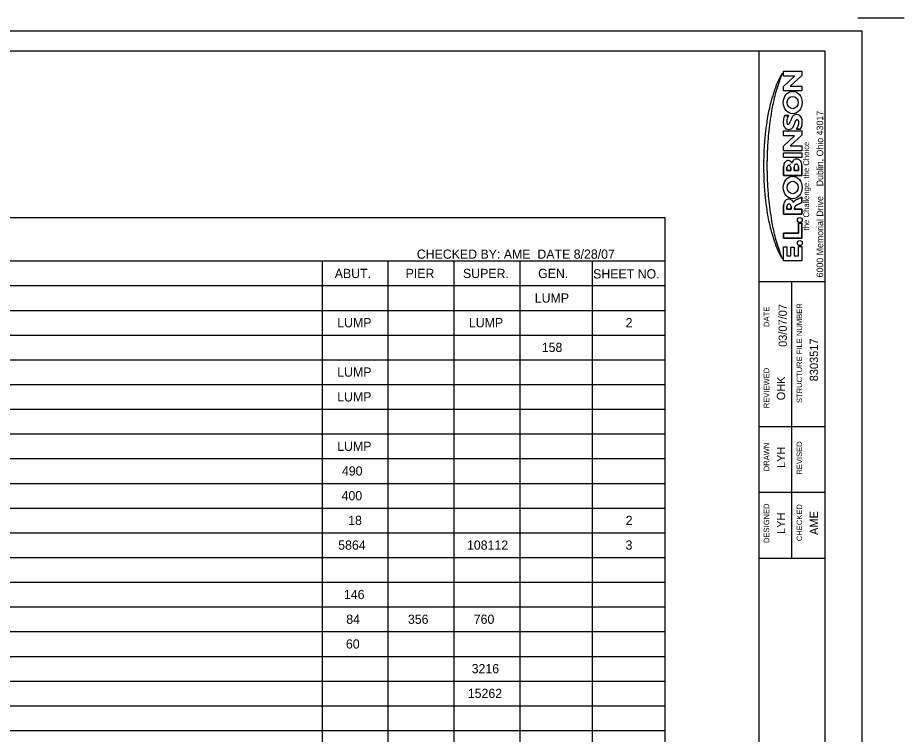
# Model space of a CAD drawing. Extents: x -70.8 to -34.9, y -11.1 to 10.9.
# Drawn here: x -48.33 to -34.87, y -0.02 to 10.86 of the extents above; entities that cross this region are included whole.
import ezdxf

# ---------------------------------------------------------------- set-up
doc = ezdxf.new("R2010")
doc.units = 0
for name, color, linetype in [('BR_P_Gen_Ground_Slope', 7, 'Continuous'), ('BR_P_Gen_Text', 7, 'Continuous'), ('Default', 7, 'Continuous'), ('SH_Border', 7, 'Continuous'), ('SH_Cut_Line', 7, 'Continuous'), ('SH_Data', 7, 'Continuous')]:
    doc.layers.add(name, color=color, linetype=linetype)

msp = doc.modelspace()

# ---------------------------------------------------------------- linework, layer by layer
at = {"layer": 'BR_P_Gen_Ground_Slope'}
for p, q in [((-66.205, 7.824), (-38.5, 7.824)), ((-38.5, 7.824), (-38.5, -8.584)), ((-66.205, 7.166), (-38.5, 7.166)), ((-43.705, 7.166), (-43.705, -8.584)), ((-42.705, 7.166), (-42.705, -8.584)), ((-41.705, 7.166), (-41.705, -8.584)), ((-40.705, 7.166), (-40.705, -8.584)), ((-39.603, 7.166), (-39.603, -8.584)), ((-66.205, 6.791), (-38.5, 6.791)), ((-66.205, 6.416), (-38.5, 6.416)), ((-66.205, 6.041), (-38.5, 6.041)), ((-66.205, 5.666), (-38.5, 5.666)), ((-66.205, 5.291), (-38.5, 5.291)), ((-66.205, 4.916), (-38.5, 4.916)), ((-66.205, 4.541), (-38.5, 4.541)), ((-66.205, 4.166), (-38.5, 4.166)), ((-66.205, 3.791), (-38.5, 3.791)), ((-66.205, 3.416), (-38.5, 3.416)), ((-66.205, 3.041), (-38.5, 3.041)), ((-66.205, 2.666), (-38.5, 2.666)), ((-66.205, 2.291), (-38.5, 2.291)), ((-66.205, 1.916), (-38.5, 1.916)), ((-66.205, 1.541), (-38.5, 1.541)), ((-66.205, 1.166), (-38.5, 1.166)), ((-66.205, 0.791), (-38.5, 0.791)), ((-66.205, 0.416), (-38.5, 0.416)), ((-66.205, 0.041), (-38.5, 0.041))]:
    msp.add_line(p, q, dxfattribs=at)
at = {"layer": 'Default'}
for p, q in [((-36.442, 9.166), (-36.504, 9.166)), ((-36.504, 9.166), (-36.442, 9.166)), ((-36.698, 8.462), (-36.698, 8.597)), ((-36.647, 8.583), (-36.647, 8.537)), ((-36.647, 8.537), (-36.647, 8.583)), ((-36.42, 8.612), (-36.42, 8.462)), ((-36.42, 8.462), (-36.698, 8.462)), ((-36.648, 7.992), (-36.648, 7.949)), ((-36.648, 7.949), (-36.648, 7.992)), ((-36.648, 7.949), (-36.585, 7.949)), ((-36.585, 7.949), (-36.648, 7.949)), ((-36.585, 7.949), (-36.585, 7.992)), ((-36.585, 7.992), (-36.585, 7.949)), ((-36.42, 8.052), (-36.501, 8.013)), ((-36.501, 8.013), (-36.42, 8.052))]:
    msp.add_line(p, q, dxfattribs=at)
for points in [[(-36.42, 9.746), (-36.698, 9.746), (-36.698, 9.815), (-36.53, 9.971), (-36.698, 9.971), (-36.698, 10.046), (-36.42, 10.046), (-36.42, 9.981), (-36.597, 9.82), (-36.42, 9.82)], [(-36.42, 8.838), (-36.698, 8.838), (-36.698, 8.907), (-36.53, 9.063), (-36.698, 9.063), (-36.698, 9.138), (-36.42, 9.138), (-36.42, 9.073), (-36.597, 8.912), (-36.42, 8.912)], [(-36.698, 8.734), (-36.698, 8.808), (-36.42, 8.808), (-36.42, 8.734)], [(-36.698, 7.167), (-36.698, 7.381), (-36.647, 7.381), (-36.647, 7.242), (-36.59, 7.242), (-36.59, 7.374), (-36.538, 7.374), (-36.538, 7.242), (-36.471, 7.242), (-36.471, 7.384), (-36.42, 7.384), (-36.42, 7.167)]]:
    msp.add_lwpolyline(points, close=True, dxfattribs=at)
for points in [[(-36.681, 9.373), (-36.625, 9.373), (-36.636, 9.346)], [(-36.636, 9.346), (-36.625, 9.373), (-36.681, 9.373)], [(-36.42, 8.612), (-36.42, 8.462), (-36.698, 8.462), (-36.698, 8.597)], [(-36.698, 8.597), (-36.698, 8.462), (-36.42, 8.462)], [(-36.647, 8.537), (-36.588, 8.537), (-36.588, 8.583)], [(-36.588, 8.583), (-36.588, 8.537), (-36.647, 8.537)], [(-36.537, 8.592), (-36.537, 8.537), (-36.472, 8.537), (-36.472, 8.592)], [(-36.472, 8.592), (-36.472, 8.537), (-36.537, 8.537), (-36.537, 8.592)], [(-36.42, 8.462), (-36.42, 8.612)], [(-36.485, 8.102), (-36.42, 8.134), (-36.42, 8.052)], [(-36.42, 8.052), (-36.42, 8.134), (-36.485, 8.102)], [(-36.533, 7.971), (-36.533, 7.949), (-36.42, 7.949), (-36.42, 7.874), (-36.698, 7.874), (-36.698, 7.949), (-36.698, 8.013)], [(-36.698, 8.013), (-36.698, 7.949), (-36.698, 7.874), (-36.42, 7.874)], [(-36.648, 7.992), (-36.648, 7.949), (-36.585, 7.949), (-36.585, 7.992)], [(-36.42, 7.874), (-36.42, 7.949), (-36.533, 7.949), (-36.533, 7.971)], [(-36.698, 7.51), (-36.698, 7.585), (-36.471, 7.585), (-36.471, 7.737), (-36.42, 7.737), (-36.42, 7.51), (-36.698, 7.51)], [(-36.42, 7.737), (-36.471, 7.737), (-36.471, 7.585), (-36.698, 7.585), (-36.698, 7.51)], [(-36.698, 7.51), (-36.42, 7.51), (-36.42, 7.737)]]:
    msp.add_lwpolyline(points, dxfattribs=at)
for centre, major_axis, ratio, start_param, end_param in [((-35.936, 9.339), (0, 1.141), 0.85, 0.988431, 1.105191), ((-35.936, 9.339), (0, 1.141), 0.85, 0.988431, 1.105191), ((-75.2, 31.113), (0, 49.953), 0.85, 4.274094, 4.276309), ((-75.2, 31.113), (0, 49.953), 0.85, 4.274094, 4.276309), ((-36.488, 9.767), (0, 0.363), 0.85, 0.822588, 0.988431), ((-36.488, 9.767), (0, 0.363), 0.85, 0.822588, 0.988431), ((-35.457, 9.198), (0, 1.685), 0.85, 1.132502, 1.288747), ((-35.457, 9.198), (0, 1.685), 0.85, 1.132502, 1.288747), ((-36.359, 9.589), (0, 0.583), 0.85, 1.105191, 1.165908), ((-36.359, 9.589), (0, 0.583), 0.85, 1.105191, 1.165908), ((-34.383, 8.593), (0, 3.112), 0.85, 1.165908, 1.233316), ((-34.383, 8.593), (0, 3.112), 0.85, 1.165908, 1.233316), ((-35.174, 8.941), (0, 2.119), 0.85, 1.243005, 1.347881), ((-35.174, 8.941), (0, 2.119), 0.85, 1.243005, 1.347881), ((-33.959, 8.688), (0, 3.52), 0.85, 1.288747, 1.354281), ((-33.959, 8.688), (0, 3.52), 0.85, 1.288747, 1.354281), ((-36.56, 9.569), (0, -0.0938), 0.910305, 4.71238898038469, 4.712389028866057), ((-32.74, 8.494), (0, 4.963), 0.85, 1.378198, 1.448475), ((-32.74, 8.494), (0, 4.963), 0.85, 1.378198, 1.448475), ((-33.985, 8.671), (0, 3.544), 0.85, 1.360764, 1.426378), ((-33.985, 8.671), (0, 3.544), 0.85, 1.360764, 1.426378), ((-36.541, 9.273), (0, 0.19), 0.85, 1.320154, 1.737094), ((-36.541, 9.273), (0, 0.19), 0.85, 1.320154, 1.737094), ((-36.528, 9.27), (0, 0.206), 0.85, 1.108668, 1.320154), ((-36.528, 9.27), (0, 0.206), 0.85, 1.108668, 1.320154), ((-36.819, 9.44), (0, 0.176), 0.85, 4.250261, 4.3216), ((-36.819, 9.44), (0, 0.176), 0.85, 4.250261, 4.3216), ((-36.556, 9.282), (0, 0.111), 0.85, 1.456901, 1.818883), ((-36.556, 9.282), (0, 0.111), 0.85, 1.456901, 1.818883), ((-36.553, 9.282), (0, 0.115), 0.85, 1.297264, 1.456901), ((-36.553, 9.282), (0, 0.115), 0.85, 1.297264, 1.456901), ((-36.487, 9.26), (0, 0.196), 0.85, 1.114999, 1.297264), ((-36.487, 9.26), (0, 0.196), 0.85, 1.114999, 1.297264), ((-36.727, 9.34), (0, 0.165), 0.85, 4.175459, 4.396402), ((-36.727, 9.34), (0, 0.165), 0.85, 4.175459, 4.396402), ((-36.401, 9.215), (0, 0.238), 0.85, 1.030221, 1.254809), ((-36.401, 9.215), (0, 0.238), 0.85, 1.030221, 1.254809), ((-36.495, 9.281), (0, 0.11), 0.85, 0.486829, 1.030221), ((-36.495, 9.281), (0, 0.11), 0.85, 0.486829, 1.030221), ((-36.56, 9.569), (0, -0.17), 0.841969, 0, 4.84813681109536e-08), ((-36.508, 9.31), (0, 0.0761), 0.85, 0.083326, 0.486829), ((-36.508, 9.31), (0, 0.0761), 0.85, 0.083326, 0.486829), ((-36.304, 9.156), (0, 0.284), 0.85, 1.063855, 1.164639), ((-36.304, 9.156), (0, 0.284), 0.85, 1.063855, 1.164639), ((-36.492, 9.279), (0, 0.0304), 0.85, 0.715581, 1.063855), ((-36.492, 9.279), (0, 0.0304), 0.85, 0.715581, 1.063855), ((-36.503, 9.233), (0, 0.154), 0.85, 6.083659, 6.366511), ((-36.503, 9.233), (0, 0.154), 0.85, 6.083659, 6.366511), ((-36.491, 9.278), (0, 0.0317), 0.85, 0.212074, 0.715581), ((-36.491, 9.278), (0, 0.0317), 0.85, 0.212074, 0.715581), ((-36.492, 9.283), (0, 0.026), 0.85, 5.247627, 6.495259), ((-36.492, 9.283), (0, 0.026), 0.85, 5.247627, 6.495259), ((-36.489, 9.311), (0, 0.0741), 0.85, 5.529173, 6.083659), ((-36.489, 9.311), (0, 0.0741), 0.85, 5.529173, 6.083659), ((-36.509, 9.272), (0, 0.0483), 0.85, 4.86616, 5.247627), ((-36.509, 9.272), (0, 0.0483), 0.85, 4.86616, 5.247627), ((-36.509, 9.286), (0, 0.109), 0.85, 4.887723, 5.529173), ((-36.509, 9.286), (0, 0.109), 0.85, 4.887723, 5.529174), ((-36.589, 9.269), (0, 0.205), 0.85, 4.51081, 4.887723), ((-36.589, 9.269), (0, 0.205), 0.85, 4.51081, 4.887723), ((-35.406, 8.848), (0, 1.866), 0.85, 1.391456, 1.496401), ((-35.406, 8.848), (0, 1.866), 0.85, 1.391456, 1.496401), ((-36.609, 9.26), (0, 0.11), 0.85, 1.737094, 2.325359), ((-36.609, 9.26), (0, 0.11), 0.85, 1.737094, 2.325359), ((-36.629, 9.237), (0, 0.0764), 0.85, 2.325359, 2.878408), ((-36.629, 9.237), (0, 0.0764), 0.85, 2.325359, 2.878408), ((-36.625, 9.262), (0, 0.0279), 0.85, 1.818883, 2.384672), ((-36.625, 9.262), (0, 0.0279), 0.85, 1.818883, 2.384672), ((-36.621, 9.273), (0, 0.113), 0.85, 2.878408, 3.55749), ((-36.621, 9.273), (0, 0.113), 0.85, 2.878408, 3.55749), ((-36.63, 9.256), (0, 0.0197), 0.85, 2.384672, 3.137191), ((-36.63, 9.256), (0, 0.0197), 0.85, 2.384672, 3.137191), ((-36.63, 9.264), (0, 0.0276), 0.85, 3.137191, 4.01614), ((-36.63, 9.264), (0, 0.0276), 0.85, 3.137191, 4.01614), ((-36.658, 9.292), (0, 0.071), 0.85, 4.01614, 4.175459), ((-36.658, 9.292), (0, 0.071), 0.85, 4.01614, 4.175459), ((-36.608, 9.237), (0, 0.0738), 0.85, 3.55749, 3.971659), ((-36.608, 9.237), (0, 0.0738), 0.85, 3.55749, 3.971659), ((-36.652, 9.285), (0, 0.145), 0.85, 3.971659, 4.353371), ((-36.652, 9.285), (0, 0.145), 0.85, 3.971659, 4.353371), ((-35.918, 8.96), (0, 0.778), 0.85, 1.164639, 1.211778), ((-35.918, 8.96), (0, 0.778), 0.85, 1.164639, 1.211778), ((-36.681, 9.328), (0, 0.265), 0.85, 4.050165, 4.172563), ((-36.681, 9.328), (0, 0.265), 0.85, 4.050165, 4.172563), ((-36.758, 9.382), (0, 0.37), 0.85, 4.172563, 4.251833), ((-36.758, 9.382), (0, 0.37), 0.85, 4.172563, 4.251833), ((-36.554, 9.264), (0, 0.103), 0.85, 4.251833, 4.86616), ((-36.554, 9.264), (0, 0.103), 0.85, 4.251833, 4.86616), ((-36.547, 9.255), (0, 0.152), 0.85, 4.087438, 4.318356), ((-36.547, 9.255), (0, 0.152), 0.85, 4.087438, 4.318356), ((-36.563, 9.263), (0, 0.173), 0.85, 4.318356, 4.51081), ((-36.563, 9.263), (0, 0.173), 0.85, 4.318356, 4.51081), ((-31.142, 8.427), (0, 6.84), 0.85, 1.472392, 1.505619), ((-31.142, 8.427), (0, 6.84), 0.85, 1.472392, 1.505619), ((-35.204, 8.747), (0, 2.111), 0.85, 1.456986, 1.558686), ((-35.204, 8.747), (0, 2.111), 0.85, 1.456986, 1.558686), ((-33.396, 8.554), (0, 4.243), 0.85, 1.519271, 1.558345), ((-33.396, 8.554), (0, 4.243), 0.85, 1.519271, 1.558345), ((-33.598, 8.616), (0, 3.944), 0.85, 1.505619, 1.553601), ((-33.598, 8.616), (0, 3.944), 0.85, 1.505619, 1.553601), ((-35.049, 8.645), (0, 2.237), 0.85, 1.553601, 1.587991), ((-35.049, 8.645), (0, 2.237), 0.85, 1.553601, 1.587991), ((-36.593, 8.595), (0, 0.124), 0.85, 1.228703, 1.558605), ((-36.593, 8.595), (0, 0.124), 0.85, 1.228703, 1.558605), ((-36.593, 8.595), (0, 0.124), 0.85, 1.228703, 1.558605), ((-36.627, 8.606), (0, 0.0833), 0.85, 0.473795, 1.194239), ((-36.627, 8.606), (0, 0.0833), 0.85, 0.473795, 1.194239), ((-36.627, 8.606), (0, 0.0833), 0.85, 0.473795, 1.194239), ((-36.629, 8.62), (0, 0.0696), 0.85, 5.943917, 6.808987), ((-36.629, 8.62), (0, 0.0696), 0.85, 5.943917, 6.808987), ((-36.629, 8.62), (0, 0.0696), 0.85, 5.943917, 6.808987), ((-36.631, 8.613), (0, 0.0776), 0.85, 5.231996, 5.947796), ((-36.631, 8.613), (0, 0.0776), 0.85, 5.231996, 5.947796), ((-36.631, 8.613), (0, 0.0776), 0.85, 5.231996, 5.947795), ((-36.501, 8.622), (0, 0.0906), 0.85, 0.462144, 1.247207), ((-36.501, 8.622), (0, 0.0906), 0.85, 0.462144, 1.247207), ((-36.501, 8.622), (0, 0.0906), 0.85, 0.462144, 1.247207), ((-36.503, 8.594), (0, 0.0402), 0.85, 0.503186, 1.629765), ((-36.503, 8.594), (0, 0.0402), 0.85, 0.503186, 1.629765), ((-36.5, 8.614), (0, 0.0982), 0.85, 6.14188, 6.715345), ((-36.5, 8.614), (0, 0.0982), 0.85, 6.14188, 6.715345), ((-36.5, 8.614), (0, 0.0982), 0.85, 6.14188, 6.715345), ((-36.505, 8.598), (0, 0.0358), 0.85, 6.277029, 6.794667), ((-36.505, 8.598), (0, 0.0358), 0.85, 6.277029, 6.794667), ((-36.504, 8.598), (0, 0.0358), 0.85, 5.771704, 6.289341), ((-36.504, 8.598), (0, 0.0358), 0.85, 5.771704, 6.289341), ((-36.506, 8.594), (0, 0.0402), 0.85, 4.65342, 5.779999), ((-36.506, 8.594), (0, 0.0402), 0.85, 4.65342, 5.779999), ((-36.496, 8.623), (0, 0.0885), 0.85, 5.535543, 6.182102), ((-36.496, 8.623), (0, 0.0885), 0.85, 5.535543, 6.182102), ((-36.496, 8.623), (0, 0.0885), 0.85, 5.535543, 6.182102), ((-36.491, 8.627), (0, 0.0818), 0.85, 4.885157, 5.560215), ((-36.491, 8.627), (0, 0.0818), 0.85, 4.885157, 5.560215), ((-36.491, 8.627), (0, 0.0818), 0.85, 4.885157, 5.560215), ((-36.591, 8.605), (0, 0.202), 0.85, 4.750784, 4.89449), ((-36.591, 8.605), (0, 0.202), 0.85, 4.750784, 4.89449), ((-36.591, 8.605), (0, 0.202), 0.85, 4.750784, 4.89449), ((-33.396, 8.66), (0, 4.243), 0.85, 1.583248, 1.622322), ((-33.396, 8.66), (0, 4.243), 0.85, 1.583248, 1.622322), ((-35.049, 8.568), (0, 2.237), 0.85, 1.553601, 1.587991), ((-35.049, 8.568), (0, 2.237), 0.85, 1.553601, 1.587991), ((-33.598, 8.598), (0, 3.944), 0.85, 1.587991, 1.635974), ((-33.598, 8.598), (0, 3.944), 0.85, 1.587991, 1.635974), ((-36.619, 8.58), (0, 0.0337), 0.85, 6.249041, 7.784024), ((-36.619, 8.58), (0, 0.0337), 0.85, 6.249041, 7.784024), ((-36.617, 8.58), (0, 0.0337), 0.85, 4.782347, 6.317329), ((-36.617, 8.58), (0, 0.0337), 0.85, 4.782347, 6.317329), ((-35.204, 8.467), (0, 2.111), 0.85, 1.582906, 1.684607), ((-35.204, 8.467), (0, 2.111), 0.85, 1.582906, 1.684607), ((-35.406, 8.366), (0, 1.866), 0.85, 1.645192, 1.750137), ((-35.406, 8.366), (0, 1.866), 0.85, 1.645192, 1.750137), ((-31.142, 8.786), (0, 6.84), 0.85, 1.635974, 1.669201), ((-31.142, 8.786), (0, 6.84), 0.85, 1.635974, 1.669201), ((-36.56, 8.28), (0, -0.0938), 0.910305, 4.71238898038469, 4.712389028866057), ((-32.74, 8.72), (0, 4.963), 0.85, 1.693118, 1.763395), ((-32.74, 8.72), (0, 4.963), 0.85, 1.693118, 1.763395), ((-36.622, 8.012), (0, 0.0895), 0.85, 0.482355, 1.561069), ((-36.622, 8.012), (0, 0.0895), 0.85, 0.482355, 1.561069), ((-36.617, 8.004), (0, 0.1), 0.85, 6.102437, 6.781247), ((-36.617, 8.004), (0, 0.1), 0.85, 6.102437, 6.781247), ((-36.618, 8.016), (0, 0.0881), 0.85, 5.152888, 6.061538), ((-36.618, 8.016), (0, 0.0881), 0.85, 5.152888, 6.061538), ((-36.56, 8.28), (0, -0.17), 0.841969, 0, 4.84813681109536e-08), ((-36.501, 8.017), (0, 0.069), 0.85, 0.463729, 1.012038), ((-36.501, 8.017), (0, 0.069), 0.85, 0.463729, 1.012038), ((-36.393, 7.805), (0, 0.316), 0.85, 0.346308, 0.520291), ((-36.393, 7.805), (0, 0.316), 0.85, 0.346308, 0.520291), ((-33.985, 8.543), (0, 3.544), 0.85, 1.715214, 1.780828), ((-33.985, 8.543), (0, 3.544), 0.85, 1.715214, 1.780828), ((-36.608, 7.988), (0, 0.0467), 0.85, 1.002734, 1.50285), ((-36.608, 7.988), (0, 0.0467), 0.85, 1.002734, 1.50285), ((-36.608, 7.988), (0, 0.0467), 0.85, 1.002734, 1.50285), ((-36.617, 7.992), (0, 0.0365), 0.85, 6.259044, 7.205975), ((-36.617, 7.992), (0, 0.0365), 0.85, 6.259044, 7.205975), ((-36.617, 7.992), (0, 0.0365), 0.85, 6.259044, 7.205975), ((-36.615, 7.992), (0, 0.0365), 0.85, 5.360396, 6.307326), ((-36.615, 7.992), (0, 0.0365), 0.85, 5.360396, 6.307326), ((-36.615, 7.992), (0, 0.0365), 0.85, 5.360396, 6.307326), ((-36.624, 7.988), (0, 0.0467), 0.85, 4.780335, 5.280452), ((-36.624, 7.988), (0, 0.0467), 0.85, 4.780335, 5.280452), ((-36.624, 7.988), (0, 0.0467), 0.85, 4.780335, 5.280452), ((-36.507, 7.972), (0, 0.0303), 0.85, 0.984544, 1.600686), ((-36.507, 7.972), (0, 0.0303), 0.85, 0.984544, 1.600686), ((-36.484, 7.952), (0, 0.0643), 0.85, 0.32473, 0.965239), ((-36.484, 7.952), (0, 0.0643), 0.85, 0.32473, 0.965239), ((-35.174, 8.273), (0, 2.119), 0.85, 1.793712, 1.898588), ((-35.174, 8.273), (0, 2.119), 0.85, 1.793712, 1.898588), ((-33.959, 8.526), (0, 3.52), 0.85, 1.787312, 1.852845), ((-33.959, 8.526), (0, 3.52), 0.85, 1.787312, 1.852845), ((-36.452, 7.787), (0, -0.0377), 0.965476, 4.71238898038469, 4.712389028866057), ((-34.383, 8.621), (0, 3.112), 0.85, 1.908276, 1.975684), ((-34.383, 8.621), (0, 3.112), 0.85, 1.908276, 1.975684), ((-35.457, 8.015), (0, 1.685), 0.85, 1.852845, 2.009091), ((-35.457, 8.015), (0, 1.685), 0.85, 1.852845, 2.009091), ((-36.452, 7.437), (0, -0.0377), 0.965476, 4.71238898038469, 4.712389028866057), ((-36.359, 7.624), (0, 0.583), 0.85, 1.975684, 2.036401), ((-36.359, 7.624), (0, 0.583), 0.85, 1.975684, 2.036401), ((-35.936, 7.875), (0, 1.141), 0.85, 2.036401, 2.153161), ((-35.936, 7.875), (0, 1.141), 0.85, 2.036401, 2.153161), ((-75.2, -13.899), (0, 49.953), 0.85, 5.148469, 5.150684), ((-75.2, -13.899), (0, 49.953), 0.85, 5.148469, 5.150684), ((-36.488, 7.447), (0, 0.363), 0.85, 2.153161, 2.319004), ((-36.488, 7.447), (0, 0.363), 0.85, 2.153161, 2.319004)]:
    msp.add_ellipse(centre, major_axis=major_axis, ratio=ratio, start_param=start_param, end_param=end_param, dxfattribs=at)
for centre, major_axis, ratio in [((-36.56, 9.569), (0, -0.17), 0.841969), ((-36.56, 9.569), (0, -0.17), 0.841969), ((-36.56, 9.569), (0, -0.0938), 0.910305), ((-36.56, 9.569), (0, -0.0938), 0.910305), ((-36.56, 8.28), (0, -0.17), 0.841969), ((-36.56, 8.28), (0, -0.17), 0.841969), ((-36.56, 8.28), (0, -0.0938), 0.910305), ((-36.56, 8.28), (0, -0.0938), 0.910305), ((-36.452, 7.787), (0, -0.0377), 0.965476), ((-36.452, 7.437), (0, -0.0377), 0.965476), ((-36.452, 7.437), (0, -0.0377), 0.965476)]:
    msp.add_ellipse(centre, major_axis=major_axis, ratio=ratio, dxfattribs=at)
at = {"layer": 'SH_Border'}
for p, q in [((-37.071, -10.644), (-37.071, 10.356)), ((-37.071, 6.856), (-36.071, 6.856)), ((-36.571, 2.656), (-36.571, 6.856)), ((-37.071, 4.656), (-36.071, 4.656)), ((-37.071, 3.656), (-36.071, 3.656)), ((-37.071, 2.656), (-36.071, 2.656))]:
    msp.add_line(p, q, dxfattribs=at)
msp.add_lwpolyline([(-67.571, 10.356), (-36.071, 10.356), (-36.071, -10.644), (-67.571, -10.644)], close=True, dxfattribs=at)
at = {"layer": 'SH_Cut_Line'}
msp.add_line((-35.571, 10.856), (-34.866, 10.856), dxfattribs=at)
msp.add_lwpolyline([(-35.509, -10.994), (-69.509, -10.994), (-69.509, 10.656), (-35.509, 10.656)], close=True, dxfattribs=at)

# ---------------------------------------------------------------- texts
at = {"layer": 'BR_P_Gen_Text'}
for s, p in [('CHECKED BY: AME  DATE 8/28/07', (-42.267, 7.199)), ('ABUT.', (-43.513, 6.906)), ('PIER', (-42.437, 6.906)), ('SUPER.', (-41.566, 6.906)), ('GEN.', (-40.425, 6.906)), ('SHEET NO.', (-39.59, 6.9)), ('LUMP', (-40.476, 6.534)), ('LUMP', (-43.476, 6.159)), ('LUMP', (-41.476, 6.159)), ('2', (-39.096, 6.159)), ('158', (-40.37, 5.784)), ('LUMP', (-43.476, 5.409)), ('LUMP', (-43.476, 5.034)), ('LUMP', (-43.476, 4.284)), ('490', (-43.404, 3.909)), ('400', (-43.409, 3.534)), ('18', (-43.309, 3.159)), ('2', (-39.096, 3.159)), ('5864', (-43.46, 2.784)), ('108112', (-41.505, 2.784)), ('3', (-39.098, 2.784)), ('146', (-43.373, 2.034)), ('84', (-43.338, 1.659)), ('356', (-42.402, 1.659)), ('760', (-41.402, 1.659)), ('60', (-43.343, 1.284)), ('3216', (-41.434, 0.909)), ('15262', (-41.493, 0.534))]:
    msp.add_text(s, height=0.14, dxfattribs=at).set_placement(p)
at = {"layer": 'Default'}
for s, height, p in [('6000 Memorial Drive    Dublin, Ohio 43017', 0.1, (-36.097, 6.916)), ('the Challenge. the Choice', 0.0875, (-36.31, 7.629))]:
    msp.add_text(s, height=height, rotation=90, dxfattribs=at).set_placement(p)
at = {"layer": 'SH_Data'}
for s, height, p in [('.', 0.125, (-36.588, 8.61)), ("'", 0.125, (-36.255, 8.61)), ('03/07/07', 0.125, (-36.649, 5.861)), ('STRUCTURE FILE NUMBER', 0.0833, (-36.417, 5.009)), ('DATE', 0.0833, (-36.917, 6.165)), ('8303517', 0.125, (-36.175, 5.339)), ('REVIEWED', 0.0833, (-36.917, 4.931)), ('OHK', 0.125, (-36.675, 5.051)), ('DRAWN', 0.0833, (-36.917, 3.974)), ('LYH', 0.125, (-36.675, 4.023)), ('REVISED', 0.0833, (-36.417, 3.923)), ('DESIGNED', 0.0833, (-36.917, 2.885)), ('CHECKED', 0.0833, (-36.417, 2.913)), ('LYH', 0.125, (-36.675, 3.023)), ('AME', 0.125, (-36.175, 3.008))]:
    msp.add_text(s, height=height, rotation=90, dxfattribs=at).set_placement(p)

doc.saveas('drawing.dxf')
